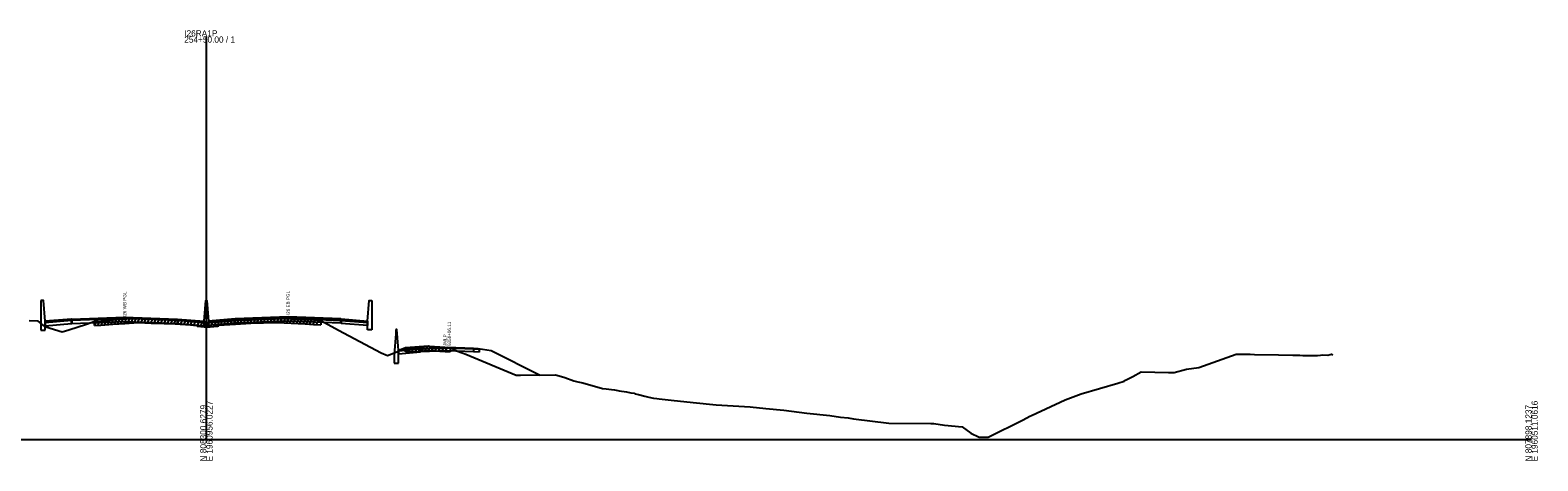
# Model space of a CAD drawing. Extents: x 1017 to 19997, y -1947 to 50737.
# Drawn here: x 10520 to 11203, y 4490 to 4685 of the extents above; entities that cross this region are included whole.
import ezdxf

# ---------------------------------------------------------------- set-up
doc = ezdxf.new("R2010")
doc.units = 0
for name, color, linetype in [('RD_GPK_XS_Cell', 7, 'Continuous'), ('RD_XS_Base', 7, 'Continuous'), ('RD_XS_ExGround', 7, 'Continuous'), ('RD_XS_ExPaveRet', 7, 'Continuous'), ('RD_XS_Greenside', 7, 'Continuous'), ('RD_XS_MedBWall', 7, 'Continuous'), ('RD_XS_Pave', 7, 'Continuous'), ('RD_XS_PaveOvlay', 7, 'Continuous'), ('RD_XS_TX_Notes', 7, 'Continuous')]:
    doc.layers.add(name, color=color, linetype=linetype)

msp = doc.modelspace()

# ---------------------------------------------------------------- linework, layer by layer
at = {"layer": 'RD_GPK_XS_Cell'}
for p, q in [((10600, 4500), (10600, 4682.26)), ((10000, 4500), (10600, 4500)), ((10600, 4500), (11200, 4500))]:
    msp.add_line(p, q, dxfattribs=at)
at = {"layer": 'RD_XS_Base'}
for points in [[(10539, 4553.71), (10527, 4552.75)], [(10539, 4552.37), (10539, 4553.71)], [(10539.05, 4553.71), (10539.05, 4552.37)], [(10539.05, 4552.37), (10563, 4553.34), (10587, 4552.37)], [(10587, 4552.37), (10587, 4553.71)], [(10599, 4552.77), (10587, 4553.71)], [(10613, 4552.5), (10613, 4553.84)], [(10660.95, 4552.5), (10637, 4553.46), (10613, 4552.5)], [(10660.95, 4552.5), (10660.95, 4553.84)], [(10661, 4553.84), (10661, 4552.5)], [(10661, 4553.83), (10673, 4552.87)], [(10661, 4552.49), (10661, 4553.83)], [(10527, 4552.75), (10527, 4551.41)], [(10527, 4551.41), (10539, 4552.37)], [(10539.05, 4552.37), (10539, 4552.37)], [(10587, 4552.37), (10599, 4551.43)], [(10599, 4551.43), (10599, 4552.77)], [(10601, 4551.56), (10601, 4552.9)], [(10613, 4552.5), (10601, 4551.56)], [(10661, 4552.5), (10660.95, 4552.5)], [(10673, 4551.53), (10661, 4552.49)], [(10673, 4552.87), (10673, 4551.53)], [(10697, 4540.89), (10687, 4540.09)], [(10687, 4540.09), (10687, 4538.76)], [(10687, 4538.76), (10697, 4539.56)], [(10697, 4540.89), (10709, 4541.37), (10721, 4540.89)], [(10697, 4539.56), (10697, 4540.89)], [(10721, 4539.58), (10709, 4540.04), (10697, 4539.56)], [(10721, 4540.89), (10721, 4539.58)], [(10721, 4540.89), (10723, 4540.81), (10723.5, 4540.79)], [(10723.5, 4539.46), (10721, 4539.58)], [(10723.5, 4540.79), (10723.5, 4539.46)]]:
    msp.add_lwpolyline(points, dxfattribs=at)
at = {"layer": 'RD_XS_ExGround'}
msp.add_lwpolyline([(10519.77, 4553.75), (10523.62, 4553.61), (10526.75, 4551.07), (10527.27, 4550.87), (10534.74, 4548.59), (10537.77, 4549.57), (10545.68, 4552.12), (10547.9, 4552.94), (10549.35, 4553.46), (10552.27, 4553.68), (10557.67, 4554.12), (10563.08, 4554.47), (10569.09, 4554.82), (10575.02, 4554.62), (10580.84, 4554.44), (10585.84, 4554.21), (10592.86, 4553.88), (10594.13, 4553.71), (10595.66, 4553.5), (10595.8, 4553.24), (10597.55, 4553.07), (10598.97, 4552.96), (10600.22, 4552.88), (10601.74, 4552.89), (10603.35, 4553.05), (10604.7, 4553.16), (10604.72, 4553.17), (10605.09, 4553.27), (10605.43, 4553.32), (10605.6, 4553.6), (10606.95, 4553.76), (10608.02, 4553.87), (10613.19, 4554.19), (10620.14, 4554.6), (10625.92, 4554.74), (10631.96, 4554.87), (10638.35, 4554.59), (10644.68, 4554.3), (10648.47, 4554.01), (10651.9, 4553.75), (10659.91, 4549.34), (10679.09, 4539.17), (10682.05, 4537.96), (10687.02, 4539.84), (10687.57, 4540.51), (10690.15, 4541.57), (10692.29, 4541.65), (10700.36, 4542.27), (10701.07, 4542.22), (10710.4, 4541.6), (10713.72, 4539.85), (10715.9, 4539.14), (10717.46, 4538.52), (10740.3, 4529.1), (10740.75, 4528.99), (10742.21, 4529.01), (10758.11, 4529.24), (10760.79, 4528.46), (10762.29, 4527.97), (10766.37, 4526.49), (10768.16, 4526.07), (10770.52, 4525.6), (10779.41, 4523.04), (10781.08, 4522.88), (10783.44, 4522.54), (10784.83, 4522.35), (10786.26, 4522.07), (10786.94, 4522), (10790.27, 4521.46), (10792.23, 4521.13), (10793.69, 4520.84), (10794.12, 4520.68), (10795.62, 4520.32), (10798.47, 4519.55), (10800.41, 4519.09), (10802.44, 4518.64), (10803.91, 4518.5), (10805.03, 4518.4), (10810.39, 4517.67), (10820.48, 4516.73), (10830.82, 4515.65), (10838.49, 4515.23), (10846.2, 4514.67), (10853.33, 4514.03), (10861.52, 4513.16), (10871.92, 4511.9), (10882.26, 4510.79), (10887.11, 4510.08), (10890.54, 4509.8), (10893, 4509.37), (10909, 4507.37), (10927.95, 4507.2), (10929.35, 4507.16), (10934.16, 4506.45), (10942.2, 4505.66), (10946.14, 4502.86), (10949.95, 4501.05), (10952.14, 4501.05), (10953.92, 4501.05), (10969.84, 4508.91), (10972.9, 4510.49), (10973.6, 4510.82), (10988.89, 4517.82), (10996.11, 4520.57), (11012.65, 4525.4), (11015.5, 4526.41), (11016.18, 4526.85), (11019.4, 4528.51), (11023.22, 4530.52), (11035.58, 4530.31), (11038.14, 4530.22), (11043.79, 4531.7), (11049.37, 4532.47), (11066.24, 4538.5), (11069.43, 4538.6), (11072.59, 4538.5), (11074.55, 4538.44), (11085.35, 4538.19), (11091.97, 4538.13), (11095.15, 4538.03), (11096.42, 4537.96), (11098.55, 4537.95), (11100.86, 4537.98), (11103.1, 4537.99), (11104.43, 4538.1), (11105.54, 4538.23), (11107.8, 4538.15), (11108.75, 4538.43), (11109.35, 4538.58), (11109.98, 4538.27)], dxfattribs=at)
at = {"layer": 'RD_XS_ExPaveRet'}
for p, q in [((10549.35, 4551.46), (10550.39, 4553.54)), ((10549.35, 4551.46), (10549.35, 4553.46)), ((10550.85, 4551.57), (10551.89, 4553.65)), ((10552.35, 4551.69), (10553.39, 4553.77)), ((10553.85, 4551.81), (10554.89, 4553.89)), ((10555.35, 4551.93), (10556.39, 4554.01)), ((10556.85, 4552.05), (10557.89, 4554.13)), ((10558.35, 4552.16), (10559.38, 4554.23)), ((10559.85, 4552.26), (10560.88, 4554.33)), ((10561.35, 4552.36), (10562.38, 4554.42)), ((10562.85, 4552.45), (10563.88, 4554.51)), ((10564.35, 4552.54), (10565.38, 4554.6)), ((10565.85, 4552.63), (10566.88, 4554.69)), ((10567.35, 4552.72), (10568.38, 4554.78)), ((10568.85, 4552.81), (10569.84, 4554.8)), ((10570.35, 4552.78), (10571.33, 4554.75)), ((10571.85, 4552.73), (10572.83, 4554.7)), ((10573.35, 4552.68), (10574.33, 4554.65)), ((10574.85, 4552.63), (10575.83, 4554.6)), ((10576.35, 4552.58), (10577.34, 4554.55)), ((10577.85, 4552.54), (10578.84, 4554.5)), ((10579.35, 4552.49), (10580.34, 4554.46)), ((10580.85, 4552.44), (10581.83, 4554.4)), ((10582.35, 4552.37), (10583.33, 4554.33)), ((10583.85, 4552.3), (10584.83, 4554.26)), ((10585.35, 4552.23), (10586.33, 4554.19)), ((10586.85, 4552.16), (10587.83, 4554.12)), ((10588.35, 4552.09), (10589.33, 4554.04)), ((10589.85, 4552.02), (10590.83, 4553.97)), ((10591.35, 4551.95), (10592.33, 4553.9)), ((10592.85, 4551.88), (10593.79, 4553.75)), ((10594.35, 4551.68), (10595.29, 4553.55)), ((10595.85, 4551.24), (10596.8, 4553.14)), ((10597.35, 4551.09), (10598.31, 4553.01)), ((10601.85, 4550.9), (10602.9, 4553.01)), ((10603.35, 4551.05), (10604.39, 4553.14)), ((10604.85, 4551.21), (10606.07, 4553.66)), ((10606.35, 4551.69), (10607.41, 4553.81)), ((10607.85, 4551.86), (10608.89, 4553.93)), ((10609.35, 4551.95), (10610.38, 4554.02)), ((10610.85, 4552.04), (10611.88, 4554.11)), ((10612.35, 4552.14), (10613.38, 4554.2)), ((10613.85, 4552.22), (10614.88, 4554.29)), ((10615.35, 4552.31), (10616.38, 4554.37)), ((10616.85, 4552.4), (10617.88, 4554.46)), ((10618.35, 4552.49), (10619.38, 4554.55)), ((10619.85, 4552.58), (10620.87, 4554.61)), ((10621.35, 4552.63), (10622.36, 4554.65)), ((10622.85, 4552.66), (10623.86, 4554.69)), ((10624.35, 4552.7), (10625.36, 4554.73)), ((10625.85, 4552.74), (10626.86, 4554.76)), ((10627.35, 4552.77), (10628.36, 4554.79)), ((10628.85, 4552.8), (10629.86, 4554.82)), ((10630.35, 4552.83), (10631.36, 4554.86)), ((10631.85, 4552.87), (10632.83, 4554.83)), ((10633.35, 4552.81), (10634.33, 4554.77)), ((10634.85, 4552.74), (10635.83, 4554.7)), ((10636.35, 4552.68), (10637.33, 4554.64)), ((10637.85, 4552.61), (10638.83, 4554.57)), ((10639.35, 4552.55), (10640.33, 4554.5)), ((10640.85, 4552.48), (10641.83, 4554.43)), ((10642.35, 4552.41), (10643.33, 4554.36)), ((10643.85, 4552.34), (10644.83, 4554.29)), ((10645.35, 4552.25), (10646.31, 4554.17)), ((10646.85, 4552.13), (10647.81, 4554.06)), ((10648.35, 4552.01), (10649.31, 4553.94)), ((10649.85, 4551.9), (10650.81, 4553.83)), ((10651.9, 4553.75), (10651.9, 4551.75)), ((10549.35, 4551.46), (10552.27, 4551.68)), ((10552.27, 4551.68), (10557.67, 4552.12)), ((10557.67, 4552.12), (10563.08, 4552.47)), ((10563.08, 4552.47), (10569.09, 4552.82)), ((10569.09, 4552.82), (10575.02, 4552.62)), ((10575.02, 4552.62), (10580.84, 4552.44)), ((10580.84, 4552.44), (10585.84, 4552.21)), ((10585.84, 4552.21), (10592.86, 4551.88)), ((10592.86, 4551.88), (10594.13, 4551.71)), ((10594.13, 4551.71), (10595.66, 4551.5)), ((10595.66, 4551.5), (10595.8, 4551.24)), ((10595.8, 4551.24), (10597.55, 4551.07)), ((10597.55, 4551.07), (10598.97, 4550.96)), ((10598.85, 4550.97), (10599.82, 4552.91)), ((10598.97, 4550.96), (10600.22, 4550.88)), ((10600.22, 4550.88), (10601.74, 4550.89)), ((10600.35, 4550.88), (10601.35, 4552.89)), ((10601.74, 4550.89), (10603.35, 4551.05)), ((10603.35, 4551.05), (10604.7, 4551.16)), ((10604.72, 4551.17), (10605.09, 4551.27)), ((10605.09, 4551.27), (10605.43, 4551.32)), ((10605.43, 4551.32), (10605.6, 4551.6)), ((10605.6, 4551.6), (10606.95, 4551.76)), ((10606.95, 4551.76), (10608.02, 4551.87)), ((10608.02, 4551.87), (10613.19, 4552.19)), ((10613.19, 4552.19), (10620.14, 4552.6)), ((10620.14, 4552.6), (10625.92, 4552.74)), ((10625.92, 4552.74), (10631.96, 4552.87)), ((10631.96, 4552.87), (10638.35, 4552.59)), ((10638.35, 4552.59), (10644.68, 4552.3)), ((10644.68, 4552.3), (10648.47, 4552.01)), ((10648.47, 4552.01), (10651.9, 4551.75)), ((10690.15, 4539.57), (10691.17, 4541.61)), ((10690.15, 4539.57), (10690.15, 4541.57)), ((10690.15, 4539.57), (10692.29, 4539.65)), ((10691.65, 4539.63), (10692.68, 4541.68)), ((10692.29, 4539.65), (10700.36, 4540.27)), ((10693.15, 4539.72), (10694.19, 4541.8)), ((10694.65, 4539.83), (10695.69, 4541.91)), ((10696.15, 4539.95), (10697.19, 4542.02)), ((10697.65, 4540.06), (10698.69, 4542.14)), ((10699.15, 4540.17), (10700.19, 4542.25)), ((10700.36, 4540.27), (10701.07, 4540.22)), ((10700.65, 4540.25), (10701.62, 4542.19)), ((10701.07, 4540.22), (10710.4, 4539.6)), ((10702.15, 4540.15), (10703.12, 4542.09)), ((10703.65, 4540.05), (10704.62, 4541.99)), ((10705.15, 4539.95), (10706.12, 4541.89)), ((10706.65, 4539.85), (10707.62, 4541.79)), ((10708.15, 4539.75), (10709.12, 4541.69)), ((10710.4, 4541.6), (10710.4, 4539.6))]:
    msp.add_line(p, q, dxfattribs=at)
at = {"layer": 'RD_XS_Greenside'}
for points in [[(10723, 4541.13), (10729, 4540.17)], [(10729, 4540.17), (10751.21, 4529.06)]]:
    msp.add_lwpolyline(points, dxfattribs=at)
at = {"layer": 'RD_XS_MedBWall'}
for points in [[(10527, 4553.43), (10526.25, 4562.77), (10525, 4562.77)], [(10525, 4562.77), (10525, 4549.43)], [(10599, 4553.43), (10599.75, 4562.89), (10600.25, 4562.89), (10601, 4553.55)], [(10673, 4553.55), (10673.75, 4562.89), (10675, 4562.89)], [(10675, 4562.89), (10675, 4549.55)], [(10527, 4549.43), (10527, 4553.43)], [(10599, 4551.43), (10599, 4553.43)], [(10601, 4553.55), (10601, 4551.43)], [(10673, 4549.55), (10673, 4553.55)], [(10525, 4549.43), (10527, 4549.43)], [(10601, 4551.43), (10599, 4551.43)], [(10675, 4549.55), (10673, 4549.55)], [(10685.75, 4547.75), (10685, 4538.41)], [(10687, 4540.41), (10686.25, 4549.75), (10685.75, 4549.75)], [(10685.75, 4549.75), (10685.75, 4547.75)], [(10687, 4534.41), (10687, 4540.41)], [(10685, 4538.41), (10685, 4534.41)], [(10685, 4534.41), (10687, 4534.41)]]:
    msp.add_lwpolyline(points, dxfattribs=at)
at = {"layer": 'RD_XS_Pave'}
for points in [[(10539, 4554.05), (10527, 4553.09)], [(10527, 4553.09), (10527, 4552.75)], [(10539, 4553.71), (10539, 4554.05)], [(10539.05, 4553.71), (10539, 4553.71)], [(10539.05, 4554.05), (10563, 4555.01), (10587, 4554.05)], [(10587, 4553.71), (10563, 4554.68), (10539.05, 4553.71)], [(10539.05, 4553.71), (10539.05, 4554.05)], [(10587, 4554.05), (10587, 4553.71)], [(10587, 4554.05), (10599, 4553.11)], [(10599, 4553.11), (10599, 4552.77)], [(10613, 4554.18), (10601, 4553.24)], [(10601, 4552.9), (10613, 4553.84)], [(10601, 4553.24), (10601, 4552.9)], [(10660.95, 4554.18), (10637, 4555.14), (10613, 4554.18)], [(10613, 4553.84), (10637, 4554.8), (10660.95, 4553.84)], [(10613, 4554.18), (10613, 4553.84)], [(10660.95, 4553.84), (10660.95, 4554.18)], [(10660.95, 4554.18), (10661, 4554.18)], [(10661, 4553.84), (10660.95, 4553.84)], [(10661, 4554.18), (10661, 4553.84)], [(10661, 4553.83), (10661, 4554.17)], [(10673, 4553.21), (10673, 4552.87)]]:
    msp.add_lwpolyline(points, dxfattribs=at)
at = {"layer": 'RD_XS_PaveOvlay'}
for points in [[(10539, 4554.39), (10527, 4553.43)], [(10527, 4553.43), (10527, 4553.09)], [(10539.05, 4554.39), (10539, 4554.39)], [(10539, 4554.39), (10539, 4554.05)], [(10539, 4554.05), (10539.05, 4554.05)], [(10539.05, 4554.39), (10563, 4555.35), (10587, 4554.39)], [(10539.05, 4554.05), (10539.05, 4554.39)], [(10587, 4554.39), (10587, 4554.05)], [(10587, 4554.39), (10599, 4553.43)], [(10599, 4553.43), (10599, 4553.11)], [(10613, 4554.51), (10601, 4553.55)], [(10601, 4553.55), (10601, 4553.24)], [(10660.95, 4554.51), (10637, 4555.47), (10613, 4554.51)], [(10613, 4554.51), (10613, 4554.18)], [(10660.95, 4554.18), (10660.95, 4554.51)], [(10660.95, 4554.51), (10661, 4554.51)], [(10661, 4554.51), (10661, 4554.18)], [(10661, 4554.51), (10673, 4553.55)], [(10661, 4554.17), (10661, 4554.51)], [(10673, 4553.21), (10661, 4554.17)], [(10673, 4553.55), (10673, 4553.21)], [(10697, 4541.21), (10687, 4540.41)], [(10687, 4540.09), (10697, 4540.89)], [(10687, 4540.41), (10687, 4540.09)], [(10697, 4541.21), (10709, 4541.69), (10721, 4541.21)], [(10721, 4540.89), (10709, 4541.37), (10697, 4540.89)], [(10697, 4540.89), (10697, 4541.21)], [(10721, 4541.21), (10721, 4540.89)], [(10721, 4541.21), (10723, 4541.13)], [(10723, 4540.81), (10721, 4540.89)], [(10723, 4541.13), (10723, 4540.81)]]:
    msp.add_lwpolyline(points, dxfattribs=at)

# ---------------------------------------------------------------- texts
at = {"layer": 'RD_GPK_XS_Cell'}
for s, p in [('I26RA1P', (10590, 4682.26)), ('254+50.00 / 1', (10590, 4679.46))]:
    msp.add_text(s, height=2.8, dxfattribs=at).set_placement(p)
for s, p in [('N 808300.6279', (10600, 4490)), ('E 1960956.0227', (10602.8, 4490)), ('N 807898.1237', (11200, 4490)), ('E 1960511.0616', (11202.8, 4490))]:
    msp.add_text(s, height=2.8, rotation=90, dxfattribs=at).set_placement(p)
at = {"layer": 'RD_XS_TX_Notes'}
for s, p in [('I26 EB PGL', (10637.75, 4556.21)), ('I26 WB PGL', (10563.75, 4555.35)), (' JMLP', (10708.77, 4541.66)), (' 9256+06.11', (10710.73, 4541.66))]:
    msp.add_text(s, height=1.5, rotation=90, dxfattribs=at).set_placement(p)

doc.saveas('drawing.dxf')
